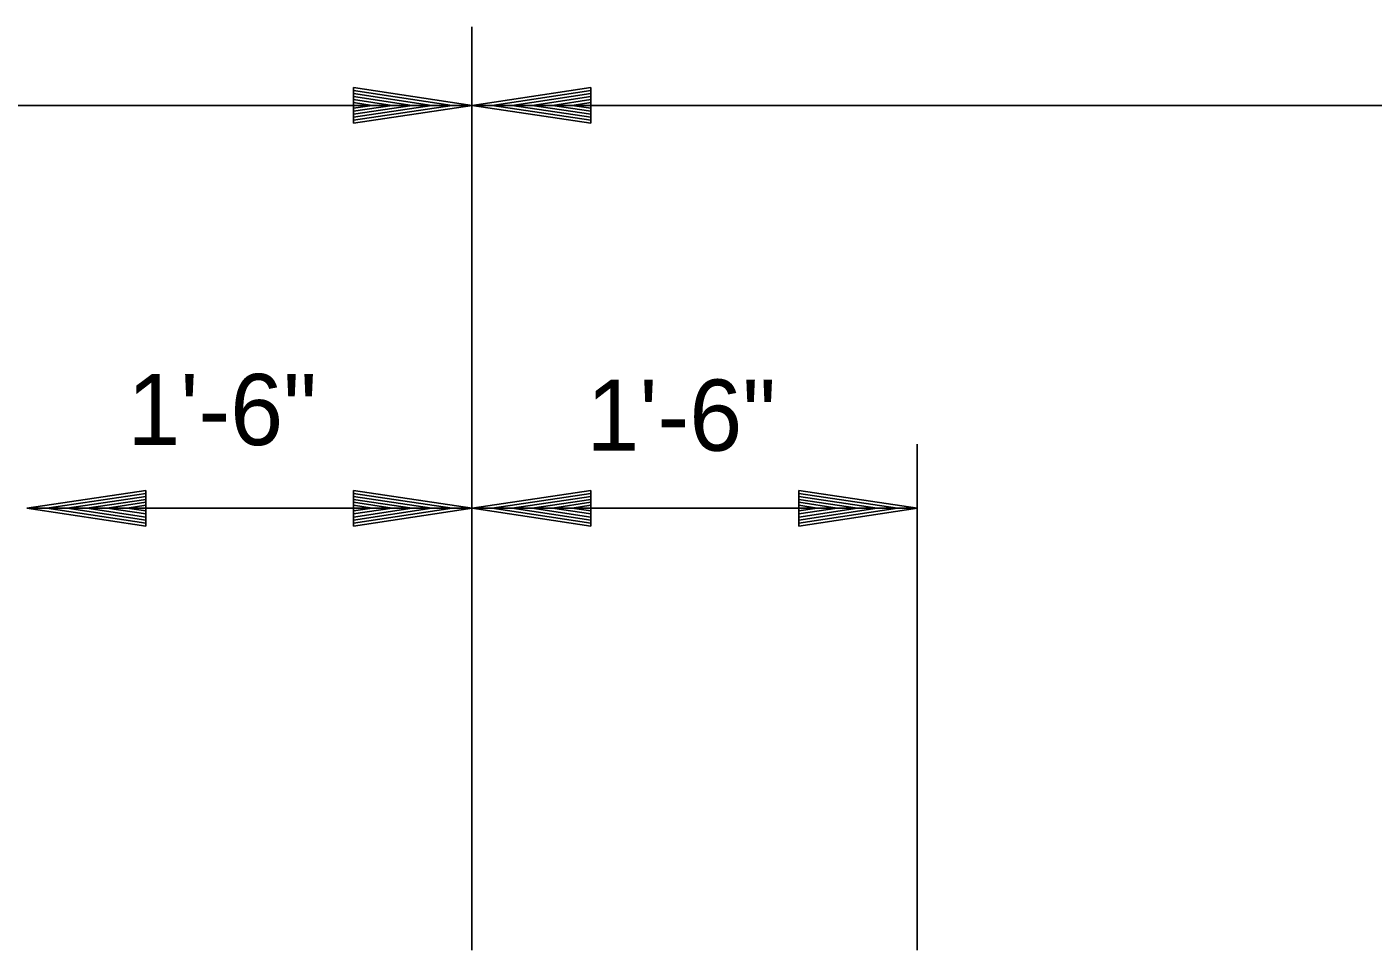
# Model space of a CAD drawing. Extents: x 1373918 to 1374069, y 381000 to 381245.
# Drawn here: x 1373972.39 to 1373983.73, y 381088.02 to 381095.8 of the extents above; entities that cross this region are included whole.
import ezdxf

# ---------------------------------------------------------------- set-up
doc = ezdxf.new("R2010")
doc.units = 0
doc.layers.add('Default', color=7, linetype='Continuous')

msp = doc.modelspace()

# ---------------------------------------------------------------- linework, layer by layer
at = {"layer": 'Default'}
for p, q in [((1373976.137, 381088.018), (1373976.137, 381095.799)), ((1373975.139, 381095.287), (1373976.139, 381095.137)), ((1373975.139, 381095.287), (1373975.139, 381094.987)), ((1373975.139, 381095.262), (1373975.971, 381095.137)), ((1373975.139, 381095.237), (1373975.799, 381095.137)), ((1373975.139, 381095.212), (1373975.634, 381095.137)), ((1373977.139, 381095.287), (1373976.139, 381095.137)), ((1373977.139, 381095.262), (1373976.306, 381095.137)), ((1373977.139, 381095.237), (1373976.476, 381095.137)), ((1373977.139, 381095.212), (1373976.644, 381095.137)), ((1373977.139, 381094.987), (1373977.139, 381095.287)), ((1373926.141, 381095.137), (1373976.137, 381095.137)), ((1373975.139, 381095.187), (1373975.464, 381095.137)), ((1373975.139, 381095.162), (1373975.296, 381095.137)), ((1373975.139, 381094.987), (1373976.139, 381095.137)), ((1373975.139, 381095.089), (1373975.464, 381095.137)), ((1373975.139, 381095.037), (1373975.799, 381095.137)), ((1373975.139, 381095.012), (1373975.971, 381095.137)), ((1373975.139, 381095.062), (1373975.634, 381095.137)), ((1373975.139, 381095.114), (1373975.296, 381095.137)), ((1373976.137, 381095.137), (1374017.385, 381095.137)), ((1373977.139, 381094.987), (1373976.139, 381095.137)), ((1373977.139, 381095.012), (1373976.306, 381095.137)), ((1373977.139, 381095.037), (1373976.476, 381095.137)), ((1373977.139, 381095.062), (1373976.644, 381095.137)), ((1373977.139, 381095.187), (1373976.814, 381095.137)), ((1373977.139, 381095.089), (1373976.814, 381095.137)), ((1373977.139, 381095.162), (1373976.981, 381095.137)), ((1373977.139, 381095.114), (1373976.981, 381095.137)), ((1373979.887, 381088.018), (1373979.887, 381092.281)), ((1373973.389, 381091.892), (1373972.389, 381091.742)), ((1373973.389, 381091.867), (1373972.557, 381091.742)), ((1373973.389, 381091.842), (1373972.727, 381091.742)), ((1373973.389, 381091.817), (1373972.894, 381091.742)), ((1373973.389, 381091.592), (1373973.389, 381091.892)), ((1373975.139, 381091.892), (1373976.139, 381091.742)), ((1373975.139, 381091.892), (1373975.139, 381091.592)), ((1373975.139, 381091.867), (1373975.971, 381091.742)), ((1373975.139, 381091.842), (1373975.799, 381091.742)), ((1373975.139, 381091.817), (1373975.634, 381091.742)), ((1373977.139, 381091.892), (1373976.139, 381091.742)), ((1373977.139, 381091.867), (1373976.306, 381091.742)), ((1373977.139, 381091.842), (1373976.476, 381091.742)), ((1373977.139, 381091.817), (1373976.644, 381091.742)), ((1373977.139, 381091.592), (1373977.139, 381091.892)), ((1373978.889, 381091.892), (1373979.889, 381091.742)), ((1373978.889, 381091.892), (1373978.889, 381091.592)), ((1373978.889, 381091.867), (1373979.721, 381091.742)), ((1373978.889, 381091.842), (1373979.549, 381091.742)), ((1373978.889, 381091.817), (1373979.384, 381091.742)), ((1373976.137, 381091.743), (1373972.388, 381091.743)), ((1373973.389, 381091.592), (1373972.389, 381091.742)), ((1373973.389, 381091.617), (1373972.557, 381091.742)), ((1373973.389, 381091.642), (1373972.727, 381091.742)), ((1373973.389, 381091.667), (1373972.894, 381091.742)), ((1373973.389, 381091.792), (1373973.064, 381091.742)), ((1373973.389, 381091.694), (1373973.064, 381091.742)), ((1373973.389, 381091.767), (1373973.232, 381091.742)), ((1373973.389, 381091.719), (1373973.232, 381091.742)), ((1373975.139, 381091.792), (1373975.464, 381091.742)), ((1373975.139, 381091.767), (1373975.296, 381091.742)), ((1373975.139, 381091.592), (1373976.139, 381091.742)), ((1373975.139, 381091.694), (1373975.464, 381091.742)), ((1373975.139, 381091.642), (1373975.799, 381091.742)), ((1373975.139, 381091.617), (1373975.971, 381091.742)), ((1373975.139, 381091.667), (1373975.634, 381091.742)), ((1373975.139, 381091.719), (1373975.296, 381091.742)), ((1373979.887, 381091.743), (1373976.137, 381091.743)), ((1373977.139, 381091.592), (1373976.139, 381091.742)), ((1373977.139, 381091.617), (1373976.306, 381091.742)), ((1373977.139, 381091.642), (1373976.476, 381091.742)), ((1373977.139, 381091.667), (1373976.644, 381091.742)), ((1373977.139, 381091.792), (1373976.814, 381091.742)), ((1373977.139, 381091.694), (1373976.814, 381091.742)), ((1373977.139, 381091.767), (1373976.981, 381091.742)), ((1373977.139, 381091.719), (1373976.981, 381091.742)), ((1373978.889, 381091.792), (1373979.214, 381091.742)), ((1373978.889, 381091.767), (1373979.046, 381091.742)), ((1373978.889, 381091.592), (1373979.889, 381091.742)), ((1373978.889, 381091.694), (1373979.214, 381091.742)), ((1373978.889, 381091.642), (1373979.549, 381091.742)), ((1373978.889, 381091.617), (1373979.721, 381091.742)), ((1373978.889, 381091.667), (1373979.384, 381091.742)), ((1373978.889, 381091.719), (1373979.046, 381091.742))]:
    msp.add_line(p, q, dxfattribs=at)

# ---------------------------------------------------------------- texts
for p in [(1373973.234, 381092.274), (1373977.101, 381092.227)]:
    msp.add_text('1\'-6"', height=0.6, dxfattribs=at).set_placement(p)

doc.saveas('drawing.dxf')
